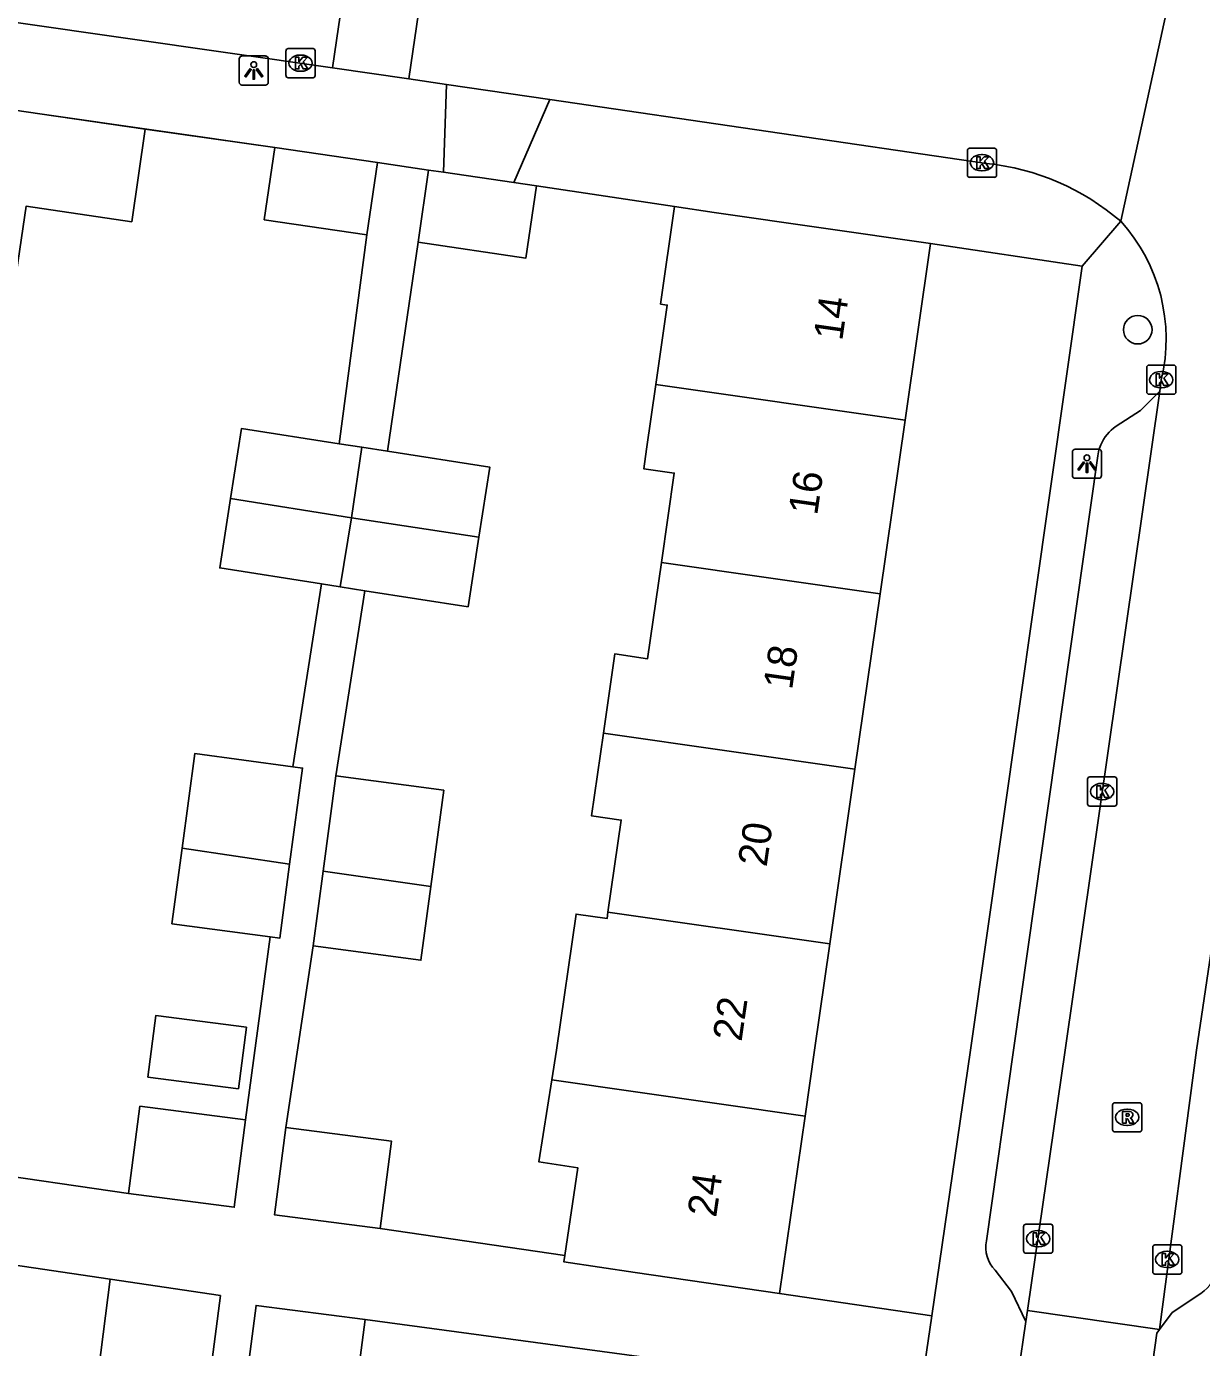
# Model space of a CAD drawing. Extents: x 163686 to 164493, y 382719 to 383870.
# Drawn here: x 163942.08 to 163982.4, y 382989.8 to 383035.14 of the extents above; entities that cross this region are included whole.
import ezdxf

# ---------------------------------------------------------------- set-up
doc = ezdxf.new("R2010")
doc.units = 0
for name, color, linetype in [('IMGEO_Boom', 7, 'Continuous'), ('IMGEO_Kolk', 7, 'Continuous'), ('IMGEO_Lichtpunt', 7, 'Continuous'), ('IMGEO_Muur', 7, 'Continuous'), ('IMGEO_Pand', 7, 'Continuous'), ('IMGEO_Pand_nummerreeks', 7, 'Continuous'), ('IMGEO_Rijbaan_lokaal_open', 7, 'Continuous'), ('IMGEO_Rioolput', 7, 'Continuous'), ('IMGEO_Voetpad_open', 7, 'Continuous')]:
    doc.layers.add(name, color=color, linetype=linetype)

msp = doc.modelspace()

# ---------------------------------------------------------------- linework, layer by layer
at = {"layer": 'IMGEO_Boom'}
msp.add_circle((163980.214, 383024.728), 0.489, dxfattribs=at)
at = {"layer": 'IMGEO_Kolk'}
for p, q in [((163950.985, 383033.45), (163950.985, 383034.302)), ((163951.06, 383034.376), (163951.912, 383034.376)), ((163951.473, 383034.156), (163951.498, 383034.156)), ((163951.986, 383034.302), (163951.986, 383033.45)), ((163951.912, 383033.376), (163951.06, 383033.376)), ((163951.496, 383033.596), (163951.471, 383033.596)), ((163974.367, 383030.032), (163974.367, 383030.884)), ((163974.442, 383030.958), (163975.294, 383030.958)), ((163974.855, 383030.738), (163974.88, 383030.738)), ((163975.368, 383030.884), (163975.368, 383030.032)), ((163974.878, 383030.178), (163974.853, 383030.178)), ((163975.294, 383029.958), (163974.442, 383029.958)), ((163980.52, 383022.586), (163980.52, 383023.438)), ((163980.595, 383023.512), (163981.447, 383023.512)), ((163981.008, 383023.292), (163981.033, 383023.292)), ((163981.521, 383023.438), (163981.521, 383022.586)), ((163981.447, 383022.512), (163980.595, 383022.512)), ((163981.031, 383022.732), (163981.006, 383022.732)), ((163978.49, 383008.453), (163978.49, 383009.305)), ((163978.565, 383009.379), (163979.417, 383009.379)), ((163979.491, 383009.305), (163979.491, 383008.453)), ((163978.978, 383009.159), (163979.003, 383009.159)), ((163979.417, 383008.379), (163978.565, 383008.379)), ((163979.001, 383008.599), (163978.976, 383008.599)), ((163976.298, 382993.105), (163976.298, 382993.957)), ((163976.373, 382994.031), (163977.225, 382994.031)), ((163976.786, 382993.811), (163976.811, 382993.811)), ((163977.299, 382993.957), (163977.299, 382993.105)), ((163977.225, 382993.031), (163976.373, 382993.031)), ((163976.809, 382993.251), (163976.784, 382993.251)), ((163980.725, 382992.393), (163980.725, 382993.245)), ((163980.8, 382993.319), (163981.652, 382993.319)), ((163981.213, 382993.099), (163981.238, 382993.099)), ((163981.726, 382993.245), (163981.726, 382992.393)), ((163981.236, 382992.539), (163981.211, 382992.539)), ((163981.652, 382992.319), (163980.8, 382992.319))]:
    msp.add_line(p, q, dxfattribs=at)
for points in [[(163950.985, 383033.45), (163950.985, 383034.302)], [(163951.06, 383034.376), (163951.912, 383034.376)], [(163951.986, 383034.302), (163951.986, 383033.45)], [(163951.306, 383034.076), (163951.429, 383034.076), (163951.429, 383033.925), (163951.559, 383034.076), (163951.723, 383034.076), (163951.577, 383033.925), (163951.73, 383033.676), (163951.578, 383033.676), (163951.493, 383033.84), (163951.429, 383033.773), (163951.429, 383033.676), (163951.306, 383033.676), (163951.306, 383034.076)], [(163951.912, 383033.376), (163951.06, 383033.376)], [(163974.367, 383030.032), (163974.367, 383030.884)], [(163974.442, 383030.958), (163975.294, 383030.958)], [(163974.688, 383030.658), (163974.811, 383030.658), (163974.811, 383030.507), (163974.941, 383030.658), (163975.105, 383030.658), (163974.959, 383030.507), (163975.112, 383030.258), (163974.96, 383030.258), (163974.875, 383030.422), (163974.811, 383030.355), (163974.811, 383030.258), (163974.688, 383030.258), (163974.688, 383030.658)], [(163975.368, 383030.884), (163975.368, 383030.032)], [(163975.294, 383029.958), (163974.442, 383029.958)], [(163980.52, 383022.586), (163980.52, 383023.438)], [(163980.595, 383023.512), (163981.447, 383023.512)], [(163981.521, 383023.438), (163981.521, 383022.586)], [(163980.841, 383023.212), (163980.964, 383023.212), (163980.964, 383023.061), (163981.094, 383023.212), (163981.258, 383023.212), (163981.112, 383023.061), (163981.265, 383022.812), (163981.113, 383022.812), (163981.028, 383022.976), (163980.964, 383022.909), (163980.964, 383022.812), (163980.841, 383022.812), (163980.841, 383023.212)], [(163981.447, 383022.512), (163980.595, 383022.512)], [(163978.49, 383008.453), (163978.49, 383009.305)], [(163978.565, 383009.379), (163979.417, 383009.379)], [(163979.491, 383009.305), (163979.491, 383008.453)], [(163978.811, 383009.079), (163978.934, 383009.079), (163978.934, 383008.928), (163979.064, 383009.079), (163979.228, 383009.079), (163979.082, 383008.928), (163979.235, 383008.679), (163979.083, 383008.679), (163978.998, 383008.843), (163978.934, 383008.776), (163978.934, 383008.679), (163978.811, 383008.679), (163978.811, 383009.079)], [(163979.417, 383008.379), (163978.565, 383008.379)], [(163976.298, 382993.105), (163976.298, 382993.957)], [(163976.373, 382994.031), (163977.225, 382994.031)], [(163977.299, 382993.957), (163977.299, 382993.105)], [(163976.619, 382993.731), (163976.742, 382993.731), (163976.742, 382993.58), (163976.872, 382993.731), (163977.036, 382993.731), (163976.89, 382993.58), (163977.043, 382993.331), (163976.891, 382993.331), (163976.806, 382993.495), (163976.742, 382993.428), (163976.742, 382993.331), (163976.619, 382993.331), (163976.619, 382993.731)], [(163977.225, 382993.031), (163976.373, 382993.031)], [(163980.725, 382992.393), (163980.725, 382993.245)], [(163980.8, 382993.319), (163981.652, 382993.319)], [(163981.046, 382993.019), (163981.169, 382993.019), (163981.169, 382992.868), (163981.299, 382993.019), (163981.463, 382993.019), (163981.317, 382992.868), (163981.47, 382992.619), (163981.318, 382992.619), (163981.233, 382992.783), (163981.169, 382992.716), (163981.169, 382992.619), (163981.046, 382992.619), (163981.046, 382993.019)], [(163981.726, 382993.245), (163981.726, 382992.393)], [(163981.652, 382992.319), (163980.8, 382992.319)]]:
    msp.add_lwpolyline(points, dxfattribs=at)
for centre, start, end in [((163951.062, 383034.3), 91.552, 178.448), ((163951.062, 383034.3), 91.552, 178.448), ((163951.91, 383034.3), 1.552, 88.448), ((163951.91, 383034.3), 1.552, 88.448), ((163951.062, 383033.452), 181.552, 268.448), ((163951.062, 383033.452), 181.552, 268.448), ((163951.91, 383033.452), 271.552, 358.448), ((163951.91, 383033.452), 271.552, 358.448), ((163974.444, 383030.882), 91.552, 178.448), ((163974.444, 383030.882), 91.552, 178.448), ((163975.292, 383030.882), 1.552, 88.448), ((163975.292, 383030.882), 1.552, 88.448), ((163974.444, 383030.034), 181.552, 268.448), ((163974.444, 383030.034), 181.552, 268.448), ((163975.292, 383030.034), 271.552, 358.448), ((163975.292, 383030.034), 271.552, 358.448), ((163980.597, 383023.436), 91.552, 178.448), ((163980.597, 383023.436), 91.552, 178.448), ((163981.445, 383023.436), 1.552, 88.448), ((163981.445, 383023.436), 1.552, 88.448), ((163980.597, 383022.588), 181.552, 268.448), ((163980.597, 383022.588), 181.552, 268.448), ((163981.445, 383022.588), 271.552, 358.448), ((163981.445, 383022.588), 271.552, 358.448), ((163978.567, 383009.303), 91.552, 178.448), ((163978.567, 383009.303), 91.552, 178.448), ((163979.415, 383009.303), 1.552, 88.448), ((163979.415, 383009.303), 1.552, 88.448), ((163978.567, 383008.455), 181.552, 268.448), ((163978.567, 383008.455), 181.552, 268.448), ((163979.415, 383008.455), 271.552, 358.448), ((163979.415, 383008.455), 271.552, 358.448), ((163976.375, 382993.955), 91.552, 178.448), ((163976.375, 382993.955), 91.552, 178.448), ((163977.223, 382993.955), 1.552, 88.448), ((163977.223, 382993.955), 1.552, 88.448), ((163976.375, 382993.107), 181.552, 268.448), ((163976.375, 382993.107), 181.552, 268.448), ((163977.223, 382993.107), 271.552, 358.448), ((163977.223, 382993.107), 271.552, 358.448), ((163980.802, 382993.243), 91.552, 178.448), ((163980.802, 382993.243), 91.552, 178.448), ((163981.65, 382993.243), 1.552, 88.448), ((163981.65, 382993.243), 1.552, 88.448), ((163980.802, 382992.395), 181.552, 268.448), ((163980.802, 382992.395), 181.552, 268.448), ((163981.65, 382992.395), 271.552, 358.448), ((163981.65, 382992.395), 271.552, 358.448)]:
    msp.add_arc(centre, 0.0765, start, end, dxfattribs=at)
for centre, major_axis, ratio, start_param, end_param in [((163951.472, 383033.876), (-0.387, 0.002), 0.722429, 4.712389, 7.853982), ((163951.497, 383033.876), (-0.39, 0.002), 0.717154, 1.570796, 4.712389), ((163974.854, 383030.458), (-0.387, 0.002), 0.722429, 4.712389, 7.853982), ((163974.879, 383030.458), (-0.39, 0.002), 0.717154, 1.570796, 4.712389), ((163981.007, 383023.012), (-0.387, 0.002), 0.722429, 4.712389, 7.853982), ((163981.032, 383023.012), (-0.39, 0.002), 0.717154, 1.570796, 4.712389), ((163978.977, 383008.879), (-0.387, 0.002), 0.722429, 4.712389, 7.853982), ((163979.002, 383008.879), (-0.39, 0.002), 0.717154, 1.570796, 4.712389), ((163976.785, 382993.531), (-0.387, 0.002), 0.722429, 4.712389, 7.853982), ((163976.81, 382993.531), (-0.39, 0.002), 0.717154, 1.570796, 4.712389), ((163981.212, 382992.819), (-0.387, 0.002), 0.722429, 4.712389, 7.853982), ((163981.237, 382992.819), (-0.39, 0.002), 0.717154, 1.570796, 4.712389)]:
    msp.add_ellipse(centre, major_axis=major_axis, ratio=ratio, start_param=start_param, end_param=end_param, dxfattribs=at)
at = {"layer": 'IMGEO_Lichtpunt'}
for p, q in [((163949.38, 383034.027), (163949.38, 383033.22)), ((163949.38, 383034.027), (163949.38, 383033.22)), ((163950.282, 383034.122), (163949.474, 383034.122)), ((163950.282, 383034.122), (163949.474, 383034.122)), ((163950.376, 383033.22), (163950.376, 383034.027)), ((163950.376, 383033.22), (163950.376, 383034.027)), ((163949.474, 383033.126), (163950.282, 383033.126)), ((163949.474, 383033.126), (163950.282, 383033.126)), ((163978.874, 383020.627), (163978.066, 383020.627)), ((163978.874, 383020.627), (163978.066, 383020.627)), ((163977.972, 383020.532), (163977.972, 383019.725)), ((163977.972, 383020.532), (163977.972, 383019.725)), ((163978.968, 383019.725), (163978.968, 383020.532)), ((163978.968, 383019.725), (163978.968, 383020.532)), ((163978.066, 383019.631), (163978.874, 383019.631)), ((163978.066, 383019.631), (163978.874, 383019.631))]:
    msp.add_line(p, q, dxfattribs=at)
for points in [[(163949.754, 383033.691), (163949.793, 383033.663), (163949.605, 383033.401), (163949.567, 383033.428), (163949.754, 383033.691)], [(163949.856, 383033.643), (163949.903, 383033.643), (163949.903, 383033.321), (163949.856, 383033.321), (163949.856, 383033.643)], [(163949.966, 383033.663), (163950.004, 383033.69), (163950.191, 383033.428), (163950.152, 383033.4), (163949.966, 383033.663)], [(163978.346, 383020.196), (163978.385, 383020.168), (163978.197, 383019.906), (163978.159, 383019.933), (163978.346, 383020.196)], [(163978.448, 383020.148), (163978.495, 383020.148), (163978.495, 383019.826), (163978.448, 383019.826), (163978.448, 383020.148)], [(163978.558, 383020.168), (163978.596, 383020.195), (163978.783, 383019.933), (163978.744, 383019.905), (163978.558, 383020.168)]]:
    msp.add_lwpolyline(points, dxfattribs=at)
for centre in [(163949.879, 383033.825), (163978.471, 383020.33)]:
    msp.add_circle(centre, 0.0994, dxfattribs=at)
for centre, start, end in [((163949.474, 383034.027), 90, 180), ((163949.474, 383034.027), 90, 180), ((163950.282, 383034.027), 0, 90), ((163950.282, 383034.027), 0, 90), ((163949.474, 383033.22), 180, 270), ((163949.474, 383033.22), 180, 270), ((163950.282, 383033.22), 270, 0), ((163950.282, 383033.22), 270, 360), ((163978.066, 383020.532), 90, 180), ((163978.066, 383020.532), 90, 180), ((163978.874, 383020.532), 0, 90), ((163978.874, 383020.532), 0, 90), ((163978.066, 383019.725), 180, 270), ((163978.066, 383019.725), 180, 270), ((163978.874, 383019.725), 270, 0), ((163978.874, 383019.725), 270, 360)]:
    msp.add_arc(centre, 0.0946, start, end, dxfattribs=at)
at = {"layer": 'IMGEO_Muur'}
for points in [[(163942.533, 383032.141), (163950.603, 383030.987)], [(163959.582, 383029.661), (163964.322, 383028.955)]]:
    msp.add_lwpolyline(points, dxfattribs=at)
at = {"layer": 'IMGEO_Pand'}
for points in [[(163933.722, 383033.434), (163942.533, 383032.141), (163946.156, 383031.609)], [(163946.156, 383031.609), (163945.69, 383028.435), (163942.068, 383028.967), (163941.623, 383025.931)], [(163953.761, 383027.983), (163950.238, 383028.5), (163950.603, 383030.987)], [(163950.603, 383030.987), (163954.126, 383030.47)], [(163954.126, 383030.47), (163953.761, 383027.983)], [(163955.516, 383027.732), (163955.879, 383030.205)], [(163955.879, 383030.205), (163956.386, 383030.131)], [(163958.807, 383029.775), (163956.386, 383030.131)], [(163959.582, 383029.661), (163959.219, 383027.188), (163955.516, 383027.732)], [(163958.807, 383029.775), (163959.582, 383029.661)], [(163963.674, 383022.846), (163964.066, 383025.574), (163963.841, 383025.606), (163964.322, 383028.955)], [(163964.322, 383028.955), (163965.674, 383028.754), (163973.1, 383027.688)], [(163972.228, 383021.619), (163973.1, 383027.688)], [(163963.868, 383016.739), (163964.308, 383019.806), (163963.259, 383019.955), (163963.355, 383020.625), (163963.674, 383022.846)], [(163963.674, 383022.846), (163972.228, 383021.619)], [(163971.373, 383015.662), (163972.228, 383021.619)], [(163952.814, 383020.817), (163949.461, 383021.342), (163949.085, 383018.94)], [(163952.814, 383020.817), (163953.589, 383020.696)], [(163953.589, 383020.696), (163953.234, 383018.275)], [(163953.589, 383020.696), (163954.47, 383020.558)], [(163954.47, 383020.558), (163957.98, 383020.009), (163957.604, 383017.607)], [(163949.085, 383018.94), (163948.712, 383016.552), (163952.207, 383016.005)], [(163949.085, 383018.94), (163953.234, 383018.275)], [(163953.234, 383018.275), (163952.84, 383015.906)], [(163953.234, 383018.275), (163957.604, 383017.607)], [(163957.604, 383017.607), (163957.231, 383015.219), (163953.695, 383015.772)], [(163961.875, 383010.881), (163962.266, 383013.6), (163963.394, 383013.438), (163963.868, 383016.739)], [(163963.868, 383016.739), (163971.373, 383015.662)], [(163952.207, 383016.005), (163952.84, 383015.906)], [(163952.84, 383015.906), (163953.695, 383015.772)], [(163970.509, 383009.643), (163971.373, 383015.662)], [(163961.875, 383010.881), (163961.468, 383008.047), (163962.487, 383007.9), (163962.034, 383004.744)], [(163970.509, 383009.643), (163961.875, 383010.881)], [(163947.418, 383006.931), (163947.853, 383010.179), (163951.222, 383009.726)], [(163951.222, 383009.726), (163951.553, 383009.682), (163951.111, 383006.39)], [(163952.26, 383006.146), (163952.699, 383009.421)], [(163952.699, 383009.421), (163956.399, 383008.925), (163955.956, 383005.616)], [(163969.648, 383003.652), (163970.509, 383009.643)], [(163950.438, 383003.887), (163947.07, 383004.339), (163947.418, 383006.931)], [(163951.111, 383006.39), (163947.418, 383006.931)], [(163951.111, 383006.39), (163950.77, 383003.843), (163950.438, 383003.887)], [(163951.916, 383003.582), (163952.26, 383006.146)], [(163952.26, 383006.146), (163955.956, 383005.616)], [(163955.956, 383005.616), (163955.616, 383003.086), (163951.916, 383003.582)], [(163960.11, 382998.989), (163960.269, 382999.998), (163960.94, 383004.67), (163962.001, 383004.517), (163962.034, 383004.744)], [(163962.034, 383004.744), (163969.648, 383003.652)], [(163968.797, 382997.743), (163969.124, 383000.001), (163969.648, 383003.652)], [(163949.625, 383000.794), (163946.521, 383001.196), (163946.247, 382999.08), (163949.351, 382998.679), (163949.625, 383000.794)], [(163960.553, 382992.953), (163960.997, 382995.969), (163959.666, 382996.166), (163960.11, 382998.989)], [(163960.11, 382998.989), (163968.797, 382997.743)], [(163945.583, 382995.079), (163945.972, 382998.075), (163949.596, 382997.606)], [(163949.596, 382997.606), (163949.207, 382994.609), (163945.583, 382995.079)], [(163968.797, 382997.743), (163967.915, 382991.647)], [(163954.212, 382993.887), (163950.588, 382994.356), (163950.977, 382997.353)], [(163950.977, 382997.353), (163954.601, 382996.883), (163954.212, 382993.887)], [(163967.915, 382991.647), (163962.969, 382992.375), (163960.521, 382992.736), (163960.553, 382992.953)], [(163948.336, 382988.509), (163944.548, 382988.999), (163944.955, 382992.141)], [(163948.336, 382988.509), (163948.734, 382991.58), (163944.955, 382992.141)], [(163953.698, 382990.758), (163949.958, 382991.242), (163949.583, 382988.348)], [(163953.698, 382990.758), (163953.324, 382987.863), (163949.583, 382988.348)]]:
    msp.add_lwpolyline(points, dxfattribs=at)
at = {"layer": 'IMGEO_Rijbaan_lokaal_open'}
for points in [[(163952.581, 383033.717), (163953.381, 383039.199)], [(163956.003, 383038.814), (163955.204, 383033.334)], [(163952.581, 383033.717), (163934.614, 383036.306), (163932.906, 383036.552)], [(163979.634, 383028.448), (163981.438, 383036.755)], [(163955.204, 383033.334), (163952.581, 383033.717)], [(163955.204, 383033.334), (163956.493, 383033.146)], [(163956.493, 383033.146), (163960.034, 383032.628)], [(163960.034, 383032.628), (163975.022, 383030.436)], [(163980.966, 383022.616), (163981.022, 383023.008)], [(163980.966, 383022.616), (163977.721, 383000), (163976.429, 382991.07)], [(163980.96, 382990.415), (163982.232, 383000), (163985.13, 383019.592)], [(163975.851, 382987.075), (163976.375, 382990.695)], [(163976.375, 382990.695), (163976.429, 382991.07)], [(163976.429, 382991.07), (163980.96, 382990.415)], [(163980.96, 382990.415), (163980.869, 382990.293), (163980.259, 382985.945)]]:
    msp.add_lwpolyline(points, dxfattribs=at)
for centre, radius, start, end in [((163974.137, 383022.04), 8.442, 49.3775, 83.9856), ((163975.158, 383024.409), 6.029, 346.5628, 42.0642)]:
    msp.add_arc(centre, radius, start, end, dxfattribs=at)
at = {"layer": 'IMGEO_Rioolput'}
for p, q in [((163979.349, 382997.271), (163979.349, 382998.123)), ((163979.424, 382998.197), (163980.276, 382998.197)), ((163979.837, 382997.977), (163979.862, 382997.977)), ((163980.35, 382998.123), (163980.35, 382997.271)), ((163980.276, 382997.197), (163979.424, 382997.197)), ((163979.86, 382997.417), (163979.835, 382997.417))]:
    msp.add_line(p, q, dxfattribs=at)
for points in [[(163979.349, 382997.271), (163979.349, 382998.123)], [(163979.424, 382998.197), (163980.276, 382998.197)], [(163979.938, 382997.895), (163979.686, 382997.897), (163979.686, 382997.497)], [(163980.35, 382998.123), (163980.35, 382997.271)], [(163979.686, 382997.497), (163979.81, 382997.497), (163979.81, 382997.659), (163979.821, 382997.659)], [(163979.864, 382997.816), (163979.81, 382997.816), (163979.81, 382997.735)], [(163979.81, 382997.735), (163979.862, 382997.735)], [(163979.868, 382997.63), (163979.939, 382997.497), (163980.079, 382997.497), (163980.014, 382997.623)], [(163980.276, 382997.197), (163979.424, 382997.197)]]:
    msp.add_lwpolyline(points, dxfattribs=at)
for centre, radius, start, end in [((163979.426, 382998.121), 0.0765, 91.552, 178.448), ((163979.426, 382998.121), 0.0765, 91.552, 178.448), ((163979.937, 382997.785), 0.109, 350.3612, 89.416), ((163980.274, 382998.121), 0.0765, 1.552, 88.448), ((163980.274, 382998.121), 0.0765, 1.552, 88.448), ((163979.82, 382997.606), 0.0533, 26.0293, 88.6989), ((163979.846, 382997.924), 0.19, 274.7715, 282.9687), ((163979.87, 382997.72), 0.0964, 77.0061, 93.1865), ((163979.884, 382997.777), 0.0378, 276.6634, 79.6772), ((163979.935, 382997.785), 0.112, 277.5842, 350.9817), ((163979.919, 382997.57), 0.108, 29.5134, 73.7905), ((163979.426, 382997.273), 0.0765, 181.552, 268.448), ((163979.426, 382997.273), 0.0765, 181.552, 268.448), ((163980.274, 382997.273), 0.0765, 271.552, 358.448), ((163980.274, 382997.273), 0.0765, 271.552, 358.448)]:
    msp.add_arc(centre, radius, start, end, dxfattribs=at)
for centre, major_axis, ratio, start_param, end_param in [((163979.836, 382997.697), (-0.387, 0.002), 0.722429, 4.712389, 7.853982), ((163979.861, 382997.697), (-0.39, 0.002), 0.717154, 1.570796, 4.712389)]:
    msp.add_ellipse(centre, major_axis=major_axis, ratio=ratio, start_param=start_param, end_param=end_param, dxfattribs=at)
at = {"layer": 'IMGEO_Voetpad_open'}
for points in [[(163956.386, 383030.131), (163956.493, 383033.146)], [(163960.034, 383032.628), (163958.807, 383029.775)], [(163950.603, 383030.987), (163946.156, 383031.609)], [(163955.879, 383030.205), (163954.126, 383030.47)], [(163964.322, 383028.955), (163959.582, 383029.661)], [(163978.308, 383026.911), (163979.634, 383028.448)], [(163953.761, 383027.983), (163952.814, 383020.817)], [(163955.516, 383027.732), (163954.47, 383020.558)], [(163973.1, 383027.688), (163978.308, 383026.911)], [(163978.308, 383026.911), (163974.476, 383000), (163973.144, 382990.883)], [(163979.467, 383021.415), (163980.307, 383021.96), (163980.966, 383022.616)], [(163975.026, 382993.46), (163975.953, 383000), (163978.842, 383020.396), (163978.882, 383020.611), (163978.945, 383020.779)], [(163952.207, 383016.005), (163951.222, 383009.726)], [(163953.695, 383015.772), (163952.699, 383009.421)], [(163950.438, 383003.887), (163949.596, 382997.606)], [(163951.916, 383003.582), (163950.977, 382997.353)], [(163945.583, 382995.079), (163940.224, 382995.858)], [(163954.212, 382993.887), (163960.553, 382992.953)], [(163944.955, 382992.141), (163935.429, 382993.556)], [(163976.375, 382990.695), (163975.884, 382991.722), (163975.322, 382992.457)], [(163973.144, 382990.883), (163967.915, 382991.647)], [(163982.381, 382991.65), (163981.398, 382991.004), (163980.96, 382990.415)], [(163963.102, 382989.494), (163953.698, 382990.758)], [(163972.734, 382988.079), (163973.144, 382990.883)]]:
    msp.add_lwpolyline(points, dxfattribs=at)
for centre, radius, start, end in [((163980.306, 383020.194), 1.482, 124.5021, 156.7427), ((163976.093, 382993.23), 1.092, 167.8218, 225.0624), ((163981.417, 382992.974), 1.638, 306.0585, 345.8197)]:
    msp.add_arc(centre, radius, start, end, dxfattribs=at)

# ---------------------------------------------------------------- texts
at = {"layer": 'IMGEO_Pand_nummerreeks'}
for s, rotation, p in [('14', 81.8234, (163970.071, 383024.324)), ('16', 81.8234, (163969.211, 383018.335)), ('18', 81.8234, (163968.35, 383012.349)), ('20', 81.8241, (163967.476, 383006.27)), ('22', 81.8234, (163966.616, 383000.275)), ('24', 81.7668, (163965.744, 382994.238))]:
    msp.add_text(s, height=1, rotation=rotation, dxfattribs=at).set_placement(p)

doc.saveas('drawing.dxf')
